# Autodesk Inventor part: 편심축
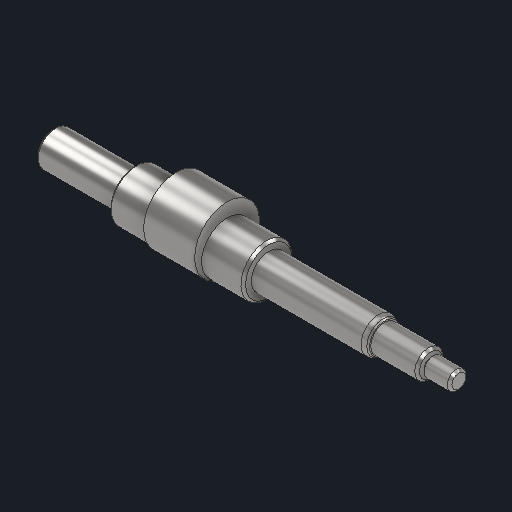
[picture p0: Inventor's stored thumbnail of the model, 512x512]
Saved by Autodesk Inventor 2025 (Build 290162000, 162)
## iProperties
Created: 2025-08
Part Number: 편심축
Material: 강철, 연강
Document SubType Name: Modeling
Designer: infra14
Density: 7.86 g/cm^3
Appearance: 기본값
Author: jhkim
Sending System: Autodesk Inventor 2026
Preprocessor: ST-DEVELOPER v20.1
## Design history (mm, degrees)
feature "솔리드1"
node "솔리드2"
